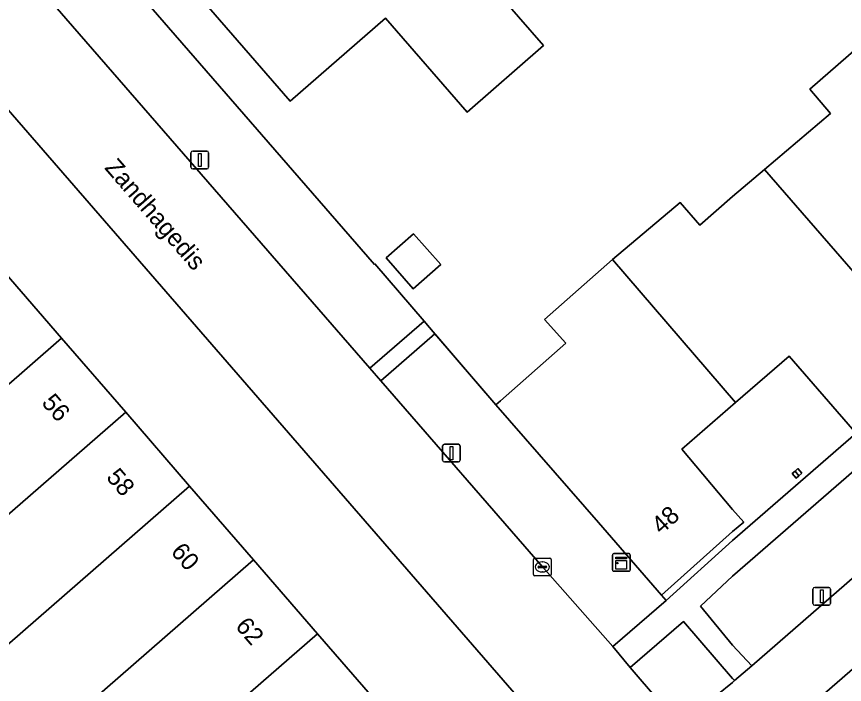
# Model space of a CAD drawing. Extents: x 155887 to 156869, y 383880 to 384678.
# Drawn here: x 155959.67 to 156006.32, y 384028.41 to 384066.02 of the extents above; entities that cross this region are included whole.
import ezdxf

# ---------------------------------------------------------------- set-up
doc = ezdxf.new("R2010")
doc.units = 0
for name, color, linetype in [('IMGEO_Erf', 7, 'Continuous'), ('IMGEO_Groenvoorziening', 7, 'Continuous'), ('IMGEO_Kast', 7, 'Continuous'), ('IMGEO_Kolk', 7, 'Continuous'), ('IMGEO_Lichtmast', 7, 'Continuous'), ('IMGEO_Muur', 7, 'Continuous'), ('IMGEO_Openbare_ruimte_label', 7, 'Continuous'), ('IMGEO_Pand', 7, 'Continuous'), ('IMGEO_Pand_nummerreeks', 7, 'Continuous'), ('IMGEO_Parkeervlak_open', 7, 'Continuous'), ('IMGEO_Rijbaan_lokaal_gesloten', 7, 'Continuous'), ('IMGEO_Rijbaan_lokaal_open', 7, 'Continuous'), ('IMGEO_Voetpad_open', 7, 'Continuous')]:
    doc.layers.add(name, color=color, linetype=linetype)

msp = doc.modelspace()

# ---------------------------------------------------------------- linework, layer by layer
at = {"layer": 'IMGEO_Erf'}
for points in [[(156014.631, 384115.561), (156000, 384102.992), (155988.995, 384093.32), (155963.356, 384071.023), (155979.834, 384052.065), (155979.862, 384052.091), (155982.633, 384048.87), (155983.24, 384048.164), (155986.681, 384044.165), (155986.936, 384044.39), (155990.609, 384047.622), (155989.411, 384048.965), (155993.239, 384052.334), (155997.053, 384055.544), (155998.161, 384054.268), (156000, 384055.886), (156001.81, 384057.418), (156005.537, 384060.572), (156004.357, 384061.931), (156008.144, 384065.22)], [(156006.776, 384042.79), (156003.203, 384046.905), (156000.175, 384044.281), (155997.145, 384041.654), (156000, 384038.252), (156000.643, 384037.54), (156000, 384037.03), (155996.007, 384033.434), (155996.263, 384033.139), (156000, 384036.51), (156086.442, 384111.494)]]:
    msp.add_lwpolyline(points, dxfattribs=at)
for points in [[(155985.059, 384060.648), (155980.452, 384065.938), (155975.087, 384061.267), (155967.872, 384069.582), (155974.675, 384075.485), (155976.643, 384073.217), (155979.506, 384075.711), (155989.361, 384064.394)], [(155951.312, 384060.458), (155954.984, 384056.223), (155958.594, 384052.061), (155962.197, 384047.907), (155965.814, 384043.736), (155969.417, 384039.582), (155973.026, 384035.42), (155976.629, 384031.266), (155980.239, 384027.103), (155984.069, 384022.687), (155988.812, 384026.65), (155955.954, 384064.477)], [(155982.023, 384050.692), (155980.488, 384052.436), (155982.032, 384053.794), (155983.567, 384052.051)], [(156003.913, 384040.306), (156003.747, 384040.16), (156003.591, 384040.023), (156003.367, 384040.279), (156003.536, 384040.427), (156003.689, 384040.562)]]:
    msp.add_lwpolyline(points, close=True, dxfattribs=at)
at = {"layer": 'IMGEO_Groenvoorziening'}
for points in [[(155979.862, 384052.091), (155979.834, 384052.065), (155963.356, 384071.023), (155960.32, 384068.383), (155979.575, 384046.214), (155982.633, 384048.87)], [(155986.681, 384044.165), (155983.24, 384048.164), (155980.186, 384045.511), (155989.295, 384035.024), (155993.268, 384030.538), (155996.263, 384033.139), (155996.007, 384033.434), (155992.451, 384037.526)]]:
    msp.add_lwpolyline(points, close=True, dxfattribs=at)
for points in [[(155997.241, 384031.955), (155994.249, 384029.363), (155995.842, 384027.506)], [(155998.247, 384027.087), (156000, 384028.524), (156000.116, 384028.622), (156000, 384028.744), (155997.241, 384031.955)]]:
    msp.add_lwpolyline(points, dxfattribs=at)
at = {"layer": 'IMGEO_Kast'}
for p, q in [((155993.24, 384034.854), (155993.24, 384035.695)), ((155993.24, 384035.695), (155993.24, 384034.854)), ((155993.315, 384035.779), (155994.156, 384035.779)), ((155994.156, 384035.779), (155993.315, 384035.779)), ((155994.24, 384035.704), (155994.24, 384034.863)), ((155994.24, 384034.863), (155994.24, 384035.704)), ((155994.165, 384034.779), (155993.324, 384034.779)), ((155993.324, 384034.779), (155994.165, 384034.779))]:
    msp.add_line(p, q, dxfattribs=at)
for points in [[(155993.435, 384035.569), (155994.035, 384035.569), (155994.035, 384035.484), (155993.435, 384035.484), (155993.435, 384035.569)], [(155993.435, 384035.394), (155994.035, 384035.394), (155994.035, 384034.905), (155993.435, 384034.905), (155993.435, 384035.394)]]:
    msp.add_lwpolyline(points, dxfattribs=at)
msp.add_circle((155993.519, 384035.243), 0.0377, dxfattribs=at)
for centre, start, end in [((155993.318, 384035.701), 92.4484, 184.2845), ((155993.318, 384035.701), 92.4484, 184.2845), ((155994.162, 384035.701), 2.4484, 94.2845), ((155994.162, 384035.701), 2.4484, 94.2845), ((155993.318, 384034.857), 182.4484, 274.2845), ((155993.318, 384034.857), 182.4484, 274.2845), ((155994.162, 384034.857), 272.4484, 4.2845), ((155994.162, 384034.857), 272.4484, 4.2845)]:
    msp.add_arc(centre, 0.0779, start, end, dxfattribs=at)
at = {"layer": 'IMGEO_Kolk'}
for p, q in [((155988.793, 384034.598), (155988.793, 384035.45)), ((155988.868, 384035.524), (155989.72, 384035.524)), ((155989.794, 384035.45), (155989.794, 384034.598)), ((155989.052, 384035.018), (155989.052, 384035.03)), ((155989.49, 384034.981), (155989.092, 384034.981)), ((155989.095, 384035.067), (155989.493, 384035.067)), ((155989.281, 384035.304), (155989.306, 384035.304)), ((155989.536, 384035.03), (155989.536, 384035.018)), ((155989.72, 384034.524), (155988.868, 384034.524)), ((155989.304, 384034.744), (155989.279, 384034.744))]:
    msp.add_line(p, q, dxfattribs=at)
for points in [[(155988.793, 384034.598), (155988.793, 384035.45)], [(155988.868, 384035.524), (155989.72, 384035.524)], [(155989.794, 384035.45), (155989.794, 384034.598)], [(155989.72, 384034.524), (155988.868, 384034.524)]]:
    msp.add_lwpolyline(points, dxfattribs=at)
for centre, radius, start, end in [((155988.87, 384035.448), 0.0765, 91.552, 178.448), ((155988.87, 384035.448), 0.0765, 91.552, 178.448), ((155989.718, 384035.448), 0.0765, 1.552, 88.448), ((155989.718, 384035.448), 0.0765, 1.552, 88.448), ((155989.092, 384035.027), 0.0403, 85.8775, 175.7526), ((155989.089, 384035.017), 0.0366, 178.938, 274.7102), ((155989.493, 384035.024), 0.043, 264.8664, 352.4533), ((155989.497, 384035.029), 0.0386, 1.7309, 96.639), ((155988.87, 384034.6), 0.0765, 181.552, 268.448), ((155988.87, 384034.6), 0.0765, 181.552, 268.448), ((155989.718, 384034.6), 0.0765, 271.552, 358.448), ((155989.718, 384034.6), 0.0765, 271.552, 358.448)]:
    msp.add_arc(centre, radius, start, end, dxfattribs=at)
for centre, major_axis, ratio, start_param, end_param in [((155989.28, 384035.024), (-0.387, 0.002), 0.722429, 4.712389, 7.853982), ((155989.305, 384035.024), (-0.39, 0.002), 0.717154, 1.570796, 4.712389)]:
    msp.add_ellipse(centre, major_axis=major_axis, ratio=ratio, start_param=start_param, end_param=end_param, dxfattribs=at)
at = {"layer": 'IMGEO_Lichtmast'}
for p, q in [((155969.495, 384057.546), (155969.495, 384058.346)), ((155969.495, 384058.346), (155969.495, 384057.546)), ((155969.595, 384058.446), (155970.385, 384058.446)), ((155970.385, 384058.446), (155969.595, 384058.446)), ((155970.485, 384058.346), (155970.485, 384057.546)), ((155970.485, 384057.546), (155970.485, 384058.346)), ((155970.385, 384057.446), (155969.595, 384057.446)), ((155969.595, 384057.446), (155970.385, 384057.446)), ((155983.771, 384041.938), (155984.561, 384041.938)), ((155984.561, 384041.938), (155983.771, 384041.938)), ((155983.671, 384041.038), (155983.671, 384041.838)), ((155983.671, 384041.838), (155983.671, 384041.038)), ((155984.661, 384041.838), (155984.661, 384041.038)), ((155984.661, 384041.038), (155984.661, 384041.838)), ((155984.561, 384040.938), (155983.771, 384040.938)), ((155983.771, 384040.938), (155984.561, 384040.938)), ((156004.541, 384032.97), (156004.541, 384033.77)), ((156004.541, 384033.77), (156004.541, 384032.97)), ((156004.641, 384033.87), (156005.431, 384033.87)), ((156005.431, 384033.87), (156004.641, 384033.87)), ((156005.531, 384033.77), (156005.531, 384032.97)), ((156005.531, 384032.97), (156005.531, 384033.77)), ((156005.431, 384032.87), (156004.641, 384032.87)), ((156004.641, 384032.87), (156005.431, 384032.87))]:
    msp.add_line(p, q, dxfattribs=at)
for points in [[(155969.915, 384058.321), (155970.065, 384058.321), (155970.065, 384057.571), (155969.915, 384057.571), (155969.915, 384058.321)], [(155984.091, 384041.813), (155984.241, 384041.813), (155984.241, 384041.063), (155984.091, 384041.063), (155984.091, 384041.813)], [(156004.961, 384033.745), (156005.111, 384033.745), (156005.111, 384032.995), (156004.961, 384032.995), (156004.961, 384033.745)]]:
    msp.add_lwpolyline(points, dxfattribs=at)
for centre, start, end in [((155969.595, 384058.346), 90, 180), ((155969.595, 384058.346), 90, 180), ((155970.385, 384058.346), 0, 90), ((155970.385, 384058.346), 360, 90), ((155969.595, 384057.546), 180, 270), ((155969.595, 384057.546), 180, 270), ((155970.385, 384057.546), 270, 0), ((155970.385, 384057.546), 270, 0), ((155983.771, 384041.838), 90, 180), ((155983.771, 384041.838), 90, 180), ((155984.561, 384041.838), 0, 90), ((155984.561, 384041.838), 360, 90), ((155983.771, 384041.038), 180, 270), ((155983.771, 384041.038), 180, 270), ((155984.561, 384041.038), 270, 0), ((155984.561, 384041.038), 270, 0), ((156004.641, 384033.77), 90, 180), ((156004.641, 384033.77), 90, 180), ((156005.431, 384033.77), 0, 90), ((156005.431, 384033.77), 360, 90), ((156004.641, 384032.97), 180, 270), ((156004.641, 384032.97), 180, 270), ((156005.431, 384032.97), 270, 0), ((156005.431, 384032.97), 270, 0)]:
    msp.add_arc(centre, 0.1, start, end, dxfattribs=at)
at = {"layer": 'IMGEO_Muur'}
msp.add_lwpolyline([(155979.862, 384052.091), (155986.681, 384044.165)], dxfattribs=at)
at = {"layer": 'IMGEO_Pand'}
for points in [[(155985.059, 384060.648), (155989.361, 384064.394), (155979.506, 384075.711), (155976.643, 384073.217), (155974.675, 384075.485), (155967.872, 384069.582), (155975.087, 384061.267), (155980.452, 384065.938)], [(156008.144, 384065.22), (156004.357, 384061.931), (156005.537, 384060.572), (156001.81, 384057.418), (156011.193, 384046.625), (156015.657, 384050.502), (156015.438, 384050.755), (156012.084, 384054.617), (156015.092, 384057.224)], [(155993.239, 384052.334), (156000.175, 384044.281), (156003.203, 384046.905), (156006.776, 384042.79), (156011.193, 384046.625), (156001.81, 384057.418), (156000, 384055.886), (155998.161, 384054.268), (155997.053, 384055.544)], [(155982.023, 384050.692), (155983.567, 384052.051), (155982.032, 384053.794), (155980.488, 384052.436)], [(155993.239, 384052.334), (155989.411, 384048.965), (155990.609, 384047.622), (155986.936, 384044.39), (155986.681, 384044.165), (155992.451, 384037.526), (155996.007, 384033.434), (156000, 384037.03), (156000.643, 384037.54), (156000, 384038.252), (155997.145, 384041.654), (156000.175, 384044.281)], [(155962.197, 384047.907), (155958.594, 384052.061), (155946.822, 384041.826), (155950.432, 384037.664)], [(155962.197, 384047.907), (155950.432, 384037.664), (155954.042, 384033.502), (155965.814, 384043.736)], [(155954.042, 384033.502), (155957.651, 384029.34), (155969.417, 384039.582), (155965.814, 384043.736)], [(156003.536, 384040.427), (156003.747, 384040.16), (156003.913, 384040.306), (156003.689, 384040.562)], [(156003.747, 384040.16), (156003.536, 384040.427), (156003.367, 384040.279), (156003.591, 384040.023)], [(155973.026, 384035.42), (155969.417, 384039.582), (155957.651, 384029.34), (155961.26, 384025.178)], [(155973.026, 384035.42), (155961.26, 384025.178), (155964.863, 384021.024), (155976.629, 384031.266)], [(155980.239, 384027.103), (155976.629, 384031.266), (155964.863, 384021.024), (155968.473, 384016.862)]]:
    msp.add_lwpolyline(points, close=True, dxfattribs=at)
at = {"layer": 'IMGEO_Parkeervlak_open'}
msp.add_lwpolyline([(156013.253, 384040.021), (156010.263, 384043.4), (156000, 384034.497), (155998.206, 384032.815), (156000, 384030.616), (156001.101, 384029.459)], close=True, dxfattribs=at)
at = {"layer": 'IMGEO_Rijbaan_lokaal_gesloten'}
for points in [[(156000, 384023.453), (156000.779, 384024.065), (156095.22, 384106.032), (156096.361, 384107.023), (156096.403, 384107.059), (156182.818, 384182.155)], [(156013.253, 384040.021), (156001.101, 384029.459), (156000.116, 384028.622), (156000, 384028.524), (155998.247, 384027.087), (155998.535, 384026.71)]]:
    msp.add_lwpolyline(points, dxfattribs=at)
at = {"layer": 'IMGEO_Rijbaan_lokaal_open'}
for points in [[(155960.32, 384068.383), (155959.065, 384069.867), (155957.105, 384072.157), (155956.757, 384071.856), (155952.631, 384068.293), (155954.621, 384065.983), (155955.954, 384064.477), (155988.812, 384026.65), (155989.25, 384026.109), (155991.717, 384023.328), (155991.361, 384023.026)], [(155995.842, 384027.506), (155994.249, 384029.363), (155993.268, 384030.538), (155989.295, 384035.024), (155980.186, 384045.511), (155979.575, 384046.214), (155960.32, 384068.383)]]:
    msp.add_lwpolyline(points, dxfattribs=at)
at = {"layer": 'IMGEO_Voetpad_open'}
for points in [[(156086.442, 384111.494), (156000, 384036.51), (155996.263, 384033.139), (155993.268, 384030.538), (155994.249, 384029.363), (155997.241, 384031.955), (156000, 384028.744), (156000.116, 384028.622), (156001.101, 384029.459), (156000, 384030.616), (155998.206, 384032.815), (156000, 384034.497), (156010.263, 384043.4)], [(156000, 384020.578), (156001.423, 384021.932), (156025.456, 384042.703), (156037.26, 384052.977), (156041.863, 384057.029), (156046.015, 384060.684), (156046.361, 384060.988), (156049.308, 384063.528), (156064.539, 384076.733), (156096.561, 384104.495), (156097.741, 384105.518), (156096.403, 384107.059), (156096.361, 384107.023), (156095.22, 384106.032), (156000.779, 384024.065), (156000, 384023.453)]]:
    msp.add_lwpolyline(points, dxfattribs=at)
msp.add_lwpolyline([(155983.24, 384048.164), (155982.633, 384048.87), (155979.575, 384046.214), (155980.186, 384045.511)], close=True, dxfattribs=at)

# ---------------------------------------------------------------- texts
at = {"layer": 'IMGEO_Openbare_ruimte_label'}
msp.add_text('Zandhagedis', height=1, rotation=310.9865, dxfattribs=at).set_placement((155964.582, 384057.486))
at = {"layer": 'IMGEO_Pand_nummerreeks'}
for s, rotation, p in [('56', 310.9335, (155961.032, 384044.244)), ('58', 310.9335, (155964.674, 384040.045)), ('48', 42.0054, (155995.998, 384036.816)), ('60', 310.9335, (155968.313, 384035.849)), ('62', 310.9335, (155971.949, 384031.657))]:
    msp.add_text(s, height=1, rotation=rotation, dxfattribs=at).set_placement(p)

doc.saveas('drawing.dxf')
